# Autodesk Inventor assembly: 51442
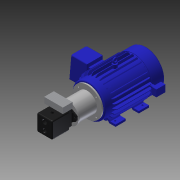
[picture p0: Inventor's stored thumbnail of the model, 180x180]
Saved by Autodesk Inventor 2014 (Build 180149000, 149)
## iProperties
Shininess: 20.0
Length Units: 11272
Angle Units: 11279
Time Units: 11290
Mass Units: 11286
Length Display Precision: 3
Angle Display Precision: 2
Company: Autodesk, Inc.
Created: 2002-07
Part Number: 51442
Project: 2035
Description: MOTOR/PUMP ASSY; 50HP
Document SubType Name: Assembly
Designer: Autodesk, Inc.
Mass: 310117 g
Surface Area: 40743.8 cm^2
Volume: 47180.1 cm^3
Density: 6.57304 g/cm^3
Density: 0.0
Volumn: 0.0
Area: 0.0
PropertySet Name: Model Information
Control State: 0
Master: False
Checked Out: False
Last Check In By: JT
Last Check In Date: 2003-06-20
Title: MOTOR/PUMP ASSY; 50 HP
Author: Autodesk, Inc.
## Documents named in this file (4)
- C:\Users\iTools\Desktop\tutorial files\Tube and Pipe\Accumulator\Parts\51442.iam
- C:\Users\iTools\Desktop\tutorial files\Tube and Pipe\Accumulator\Parts\237554.ipt
- C:\Users\iTools\Desktop\tutorial files\Tube and Pipe\Accumulator\Parts\237490.ipt
- C:\Users\iTools\Desktop\tutorial files\Tube and Pipe\Accumulator\Parts\248800.ipt
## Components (3 placed, 3 different names)
1. 248800:1 — Mate:1, Mate:2, Angle:1
2. 237554:1 — Mate:1, Mate:2, Angle:1, Mate:3, Mate:4, Mate:5
3. 237490:1 — Mate:3, Mate:4, Mate:5
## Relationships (6: Mate 5, Angle 1)
- Mate:1: 248800:1 ↔ 237554:1
- Mate:2: 248800:1 ↔ 237554:1
- Angle:1: 248800:1 ↔ 237554:1
- Mate:3: 237554:1 ↔ 237490:1
- Mate:4: 237554:1 ↔ 237490:1
- Mate:5: 237554:1 ↔ 237490:1
